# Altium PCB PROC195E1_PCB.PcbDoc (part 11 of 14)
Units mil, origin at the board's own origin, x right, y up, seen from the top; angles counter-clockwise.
Board outline 3110.24 x 2500 mil, 10 copper layers (Top Layer, L02_GND1, L03_SIG1, L04_GND2, L05_PWR1, L06_PWR2, L07_GND3, L08_SIG2, L09_GND4, Bottom Layer), stack 66.407 mil thick; 571 components, 538 nets, 6726 pads, 1286 vias.
Unrouted connection lines stored in the file: 4.
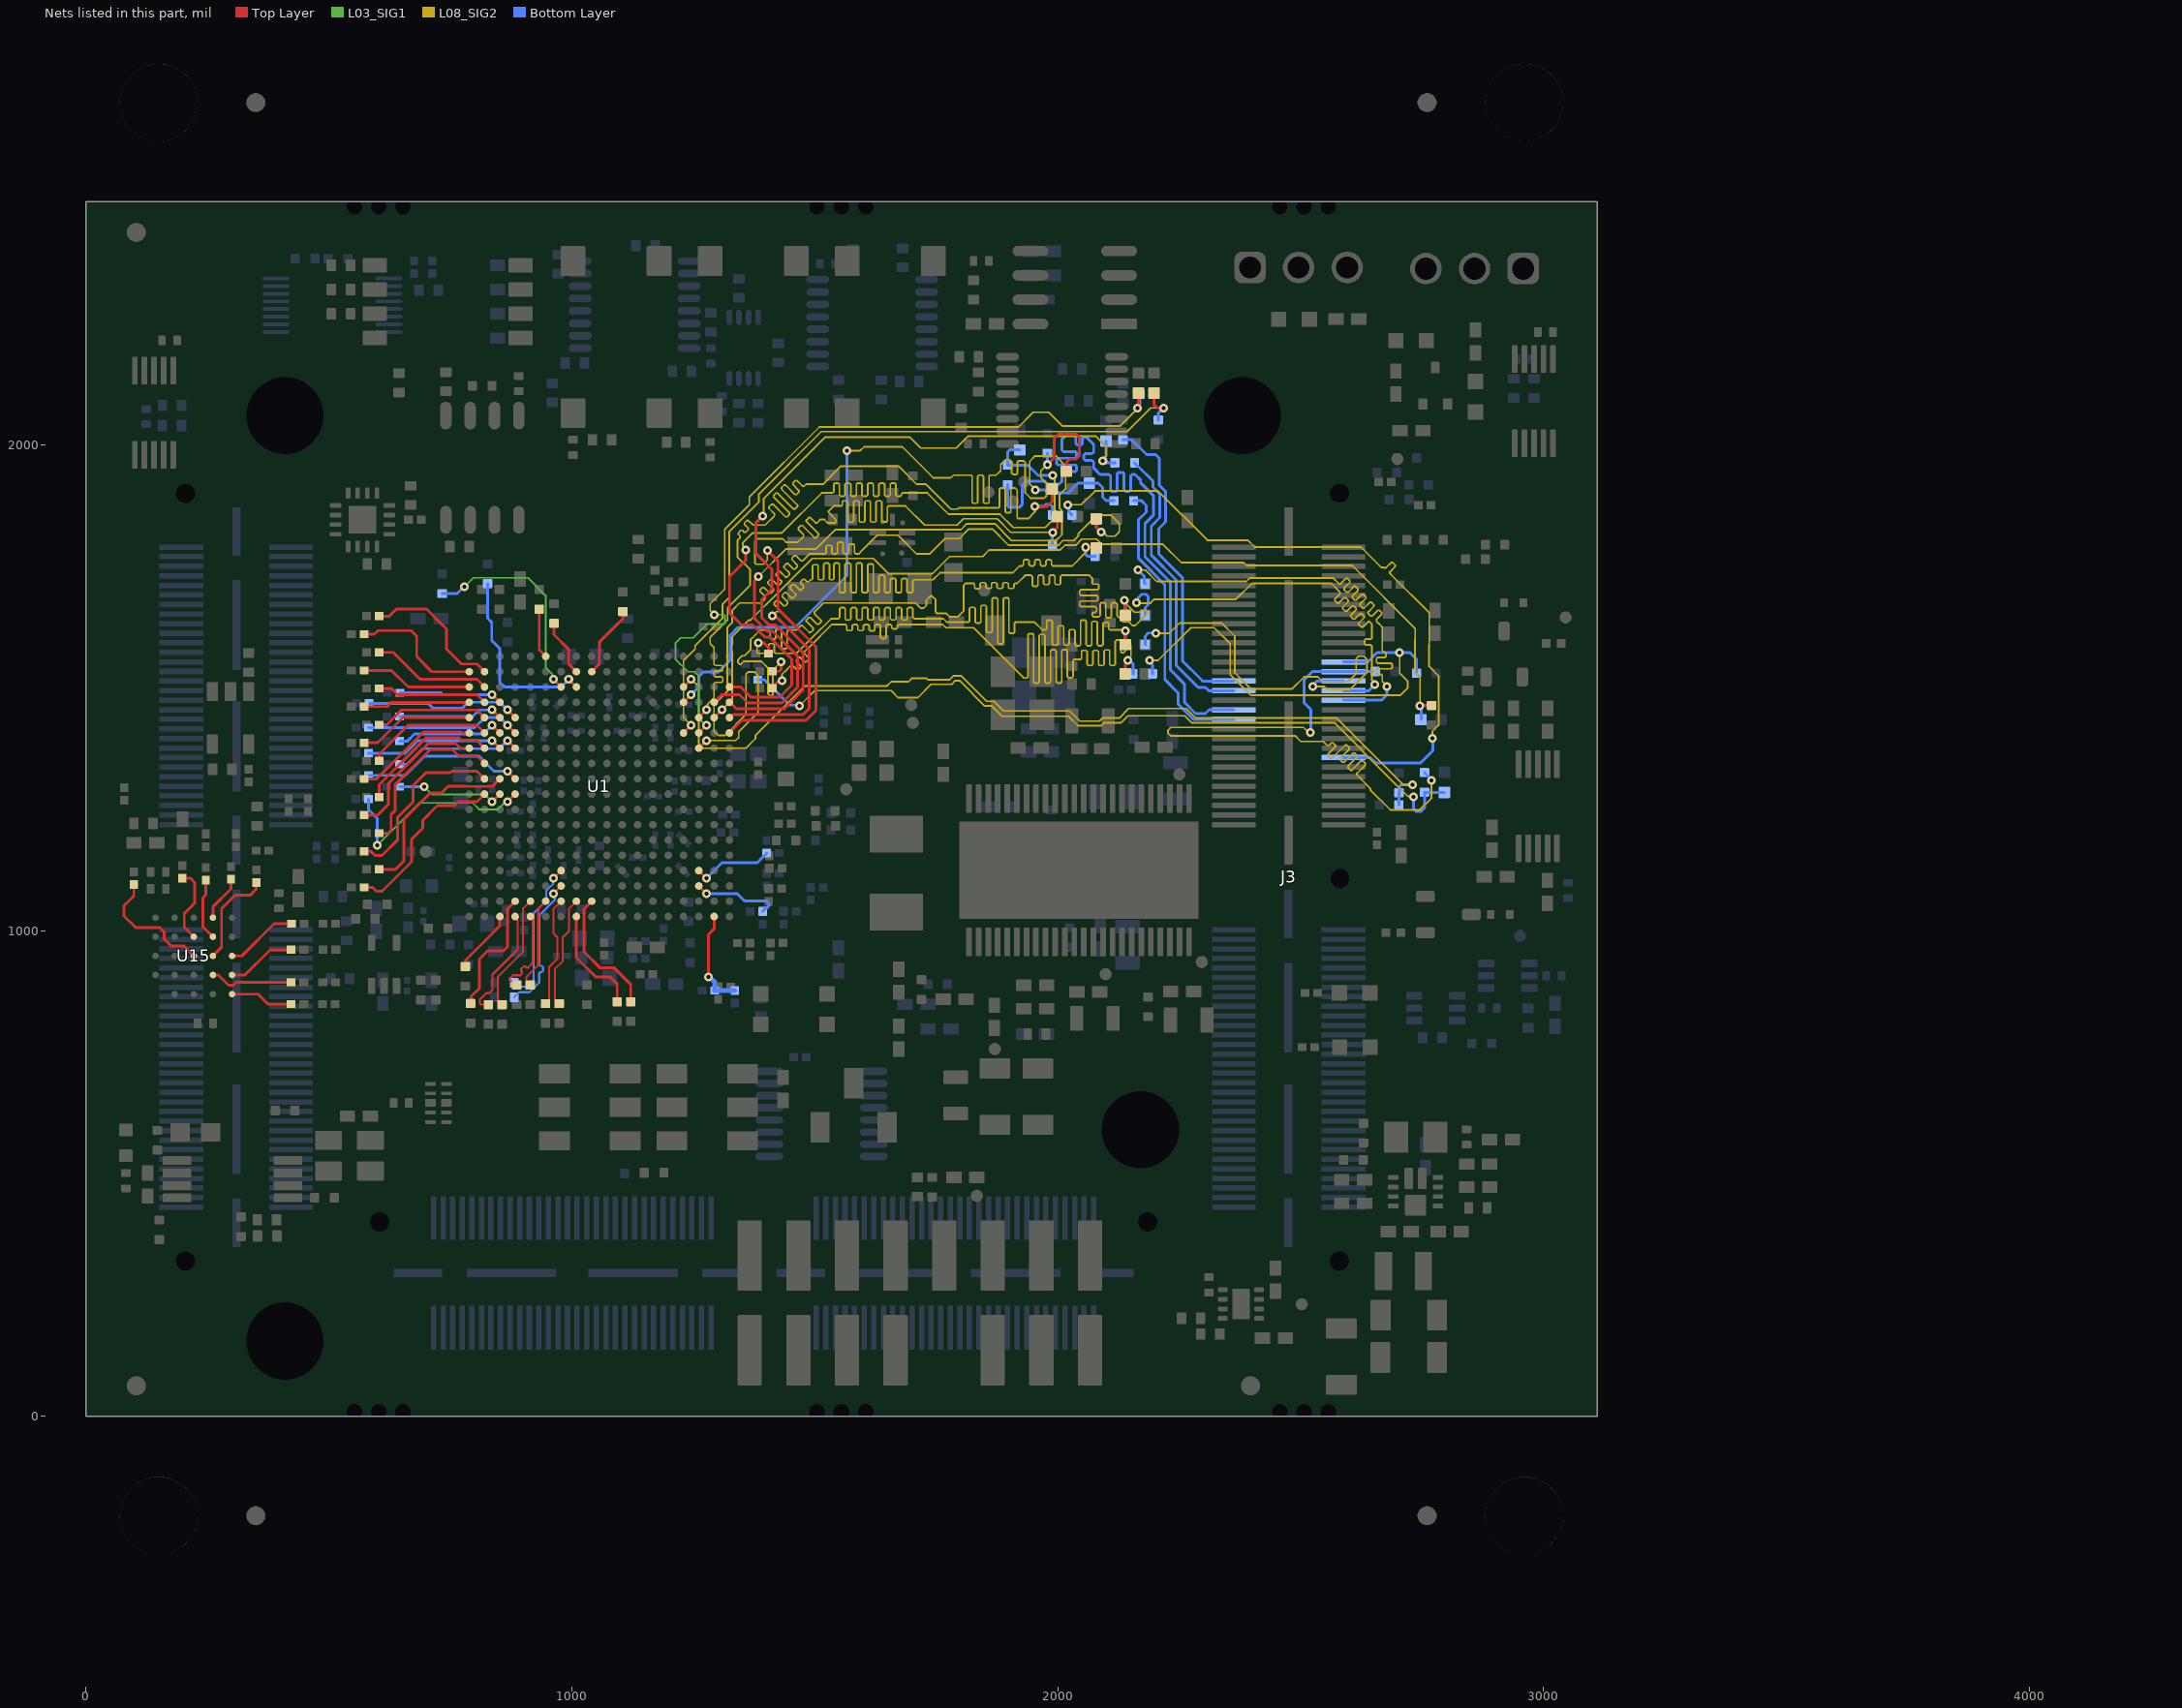
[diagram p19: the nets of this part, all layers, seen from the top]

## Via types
v1: diameter 18, hole 8, Top Layer to Bottom Layer, tented both sides, 1226 vias
v2: diameter 19.68, hole 7.87, Top Layer to Bottom Layer, tented top, 54 vias
v3: diameter 19.68, hole 7.87, Top Layer to Bottom Layer, 4 vias
v4: diameter 19.68, hole 7.87, Top Layer to Bottom Layer, tented both sides, 2 vias

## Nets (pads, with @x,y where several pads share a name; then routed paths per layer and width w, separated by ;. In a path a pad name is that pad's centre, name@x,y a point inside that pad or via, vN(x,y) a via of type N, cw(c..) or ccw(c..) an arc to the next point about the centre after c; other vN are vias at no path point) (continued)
PR0_PRU1_GPIO6: J3.76 R155.1 | length 1415.1
  L08_SIG2 w3.6: v1(2020.51,1876.46) 2048.46,1876.46 2076.8,1904.8 2206.68,1904.8 2307.9,1803.58 2391.23,1803.58 2405.46,1789.35 2624.02,1789.35 2665.54,1747.83 2670.82,1747.83 2672.1,1746.56 2675.38,1746.56 2686.24,1757.42 2689.52,1757.42 2694.44,1752.5 2694.44,1749.22 2683.58,1738.36 2683.58,1735.08 2685.81,1732.85 2687.08,1731.58 2764.58,1654.08 2764.58,1588.02 2763.9,1587.34 2763.9,1544.51 2784,1524.41 2784,1422.93 2771.15,1410.07 v1(2771.15,1396.22)
  Bottom Layer w5.8: v1(2020.51,1876.46) 2022.84,1874.13 2022.84,1862 R155.1@2029.24,1855.61 ; J3.76@2588.19,1356.08 2643.71,1356.08 2654.43,1345.36 2747.04,1345.36 2771.72,1370.04 2771.72,1395.65 v1(2771.15,1396.22)
PR0_PRU1_GPIO8: J3.89 R156.1 | length 607.7
  Bottom Layer w5.8: R156.1@2158.55,1962.95 2158.55,1962.14 2164.67,1956.01 2165.49,1956.01 2196.25,1925.25 2196.25,1912.75 2210.41,1898.59 2210.41,1850.03 2192.74,1832.37 2192.74,1773.16 2244.19,1721.71 2244.19,1545.79 2289.42,1500.56 2304.16,1500.56 2310.84,1493.88 J3.89@2362.59,1493.88
PR0_PRU1_GPIO9: J3.85 R159.1 | length 1470.9
  Bottom Layer w5.8: R159.1@1897.01,1917.7 1897.01,1874.35 1899.88,1871.47 1921.5,1871.47 1926.78,1876.76 1926.78,1915.81 1936.01,1925.04 1973.96,1925.04 1980.06,1918.94 2003.05,1918.94 2008.61,1924.49 2008.61,1941.2 2012.01,1944.59 2036.19,1944.59 2038.95,1947.35 2038.95,1955.63 2036.19,1958.39 2000.66,1958.39 1997.9,1961.15 1997.9,1969.43 2000.66,1972.19 2036.19,1972.19 2038.95,1974.95 2038.95,1983.23 2036.19,1985.99 2012.01,1985.99 2008.61,1989.39 2008.61,2005.57 2008.61,2011.34 2017.14,2019.87 2033.84,2019.87 2037.24,2016.47 2037.24,2002.63 2040,1999.87 2048.28,1999.87 2051.04,2002.63 2051.04,2012.36 2054.44,2015.76 2059.24,2015.76 2063.73,2011.28 2073.3,2001.7 2074.04,2000.96 2074.04,1985 2070.65,1981.6 2056.8,1981.6 2054.04,1978.84 2054.04,1970.56 2056.8,1967.8 2070.65,1967.8 2074.04,1964.4 2074.04,1961.32 2074.04,1952.3 2087.21,1939.14 2088.85,1939.14 2105.55,1939.14 2108.95,1935.75 2108.95,1907.19 2111.71,1904.43 2119.99,1904.43 2122.75,1907.19 2122.75,1940.45 2125.51,1943.21 2133.79,1943.21 2136.55,1940.45 2136.55,1907.19 2139.31,1904.43 2147.59,1904.43 2150.35,1907.19 2150.35,1935.75 2153.74,1939.14 2159,1939.14 2170.7,1927.44 2170.7,1921.61 2196.84,1895.47 2196.84,1854.85 2179.74,1837.75 2179.74,1769.47 2232.39,1716.82 2232.39,1536.07 2260.6,1507.86 2260.6,1470.37 2284.14,1446.83 2304.04,1446.83 2311.72,1454.51 J3.85@2362.59,1454.51
PR0_PRU1_GPIO10: J3.83 R161.1 | length 606.3
  Bottom Layer w5.8: R161.1@2156.3,1884.68 2172.55,1884.68 2182.04,1875.2 2182.04,1861.42 2166.63,1846.01 2166.63,1765.9 2220.59,1711.93 2220.59,1516.72 2247.6,1489.71 2247.6,1466.68 2279.46,1434.82 J3.83@2362.59,1434.82
PR0_PRU1_GPIO11: J3.90 R163.1 | length 974.2
  L08_SIG2 w3.6: v1(2162.42,1674.75) 2163.1,1674.08 2190.92,1674.08 2198.91,1682.07 2367.15,1682.07 2399.78,1714.7 2563.02,1714.7 2571.84,1705.89 2573.11,1704.61 2581.31,1696.41 2581.31,1693.13 2570.45,1682.27 2570.45,1678.99 2575.37,1674.07 2578.65,1674.07 2589.51,1684.93 2592.79,1684.93 2597.72,1680.01 2597.72,1676.72 2586.86,1665.86 2586.86,1662.58 2591.78,1657.66 2595.06,1657.66 2605.92,1668.52 2609.2,1668.52 2614.12,1663.6 2614.12,1660.32 2603.26,1649.46 2603.26,1646.18 2608.18,1641.26 2611.46,1641.26 2622.32,1652.12 2625.6,1652.12 2630.53,1647.2 2630.53,1643.91 2619.66,1633.05 2619.66,1629.77 2624.59,1624.85 2627.87,1624.85 2638.73,1635.71 2642.01,1635.71 2644.09,1633.63 2645.36,1632.36 2646.4,1631.32 2646.4,1629.4 ; 2646.31,1629.31 2646.31,1615.52 2646.31,1602.12 2643.99,1599.8 2633.65,1599.8 2631.33,1597.48 2631.33,1590.52 2633.65,1588.2 2643.99,1588.2 2646.31,1585.88 2646.31,1580 2646.31,1516.17 2652.54,1509.94 v1(2652.54,1506.86)
  Bottom Layer w5.8: v1(2162.42,1674.75) 2164.76,1677.09 2164.76,1683.91 2173.11,1692.26 2181.74,1692.26 2186,1688 2186,1671 2179.97,1664.97 R163.1@2179.97,1648.62 ; J3.90@2588.19,1493.88 2640.61,1493.88 2652.54,1505.81 v1(2652.54,1506.86)
PR0_PRU1_GPIO12: J3.92 R164.1 | length 869.1
  L08_SIG2 w3.6: v1(2202.52,1611.62) 2202.95,1612.04 2229.72,1612.04 2250.92,1633.24 2337.42,1633.24 2364.63,1606.03 2364.63,1530.49 2397.95,1497.17 2482.06,1497.17 2507.26,1522.38 2535.55,1522.38 2544.92,1513 2598.55,1513 2614,1528.45 2614,1559.47 2619.41,1564.87 2629.8,1564.87 2636.71,1557.96 2636.71,1531.71 2601,1496 2555,1496 2548.67,1502.33 2524.83,1502.33 v1(2524.57,1502.58)
  Bottom Layer w5.8: R164.1@2179.97,1588.62 2179.97,1606.28 2186.2,1612.51 2201.63,1612.51 v1(2202.52,1611.62) ; v1(2524.57,1502.58) 2524.57,1504.81 2533.32,1513.56 J3.92@2588.19,1513.56
PR0_PRU1_GPIO13: J3.94 R8.1 R167.1 | length 1459.6
  L08_SIG2 w3.6: v1(2520.02,1407.99) 2516.28,1407.99 2506.07,1418.19 2232.68,1418.19 2227,1412.51 2227,1406.4 2232.46,1400.94 2488.62,1400.94 2500.15,1389.41 2546.79,1389.41 2552.65,1383.55 2553.93,1382.27 2554.96,1381.24 2558.24,1381.24 2563.49,1386.5 2566.77,1386.5 2571.69,1381.58 2571.69,1378.3 2556.49,1363.09 2556.49,1359.81 2561.41,1354.89 2564.69,1354.89 2591.71,1381.91 2594.99,1381.91 2599.91,1376.98 2599.91,1373.7 2581.16,1354.95 2581.16,1351.67 2586.08,1346.75 2589.36,1346.75 2608.11,1365.5 2611.39,1365.5 2616.32,1360.58 2616.32,1357.3 2597.56,1338.55 2597.56,1335.26 2602.48,1330.34 2605.77,1330.34 2624.52,1349.1 2627.8,1349.1 2632.72,1344.17 2632.72,1340.89 2615.65,1323.83 2615.65,1320.55 2623.86,1312.34 2625.13,1311.07 2643.49,1292.71 2643.49,1289.34 2684.37,1248.46 2744.96,1248.46 2769.34,1272.83 v1(2769.33,1309.07)
  Bottom Layer w5.8: v1(2520.02,1407.99) 2521.16,1409.12 2521.16,1454.98 2506.67,1469.46 2506.67,1515.29 2524.64,1533.25 J3.94@2588.19,1533.25 R8.1@2648.07,1533.23 ; R167.1@2754.95,1325.28 2755.44,1325.28 2769.33,1311.39 v1(2769.33,1309.07)
PR0_PRU1_GPIO14: J3.96 R5.1 R169.1 | length 962.7
  L08_SIG2 w3.6: v1(2189.03,1556.43) 2207.13,1556.43 2274.34,1623.64 2321.75,1623.64 2355.03,1590.36 2355.03,1526.51 2396.83,1484.71 2706.02,1484.71 2720.23,1498.92 2720.23,1513.65 2703.82,1530.06 v1(2703.82,1572.01)
  Bottom Layer w5.8: v1(2189.03,1556.43) 2189.03,1553.62 2195.42,1547.23 R169.1@2195.42,1528.68 ; J3.96@2588.19,1552.93 2588.64,1553.38 2638.49,1553.38 2657.12,1572.01 v1(2703.82,1572.01) 2724.99,1572.01 2738.54,1558.46 R5.1@2738.54,1529.81
PR0_PRU1_GPIO15: J3.91 R170.1 | length 662
  Bottom Layer w5.8: R170.1@2134.23,2010.35 2152.6,2010.35 2183.43,1979.52 2189.7,1979.52 2201.69,1979.5 2209.1,1972.09 2209.1,1916.59 2222.21,1903.48 2222.21,1841.11 2208.23,1827.14 2208.23,1775.11 2256.6,1726.75 2256.6,1555.38 2294.73,1517.25 2298.35,1513.62 2306.41,1513.62 2306.47,1513.56 J3.91@2362.59,1513.56
PR0_PRU1_GPIO16: J3.88 R171.1 | length 1100.6
  L08_SIG2 w3.6: v1(2164.93,1742.28) 2180.51,1742.28 2204.03,1718.75 2388.56,1718.75 2395.28,1725.47 2567.52,1725.47 2577.76,1715.24 2579.03,1713.96 2582.31,1713.96 2593.17,1724.83 2596.45,1724.83 2601.38,1719.9 2601.38,1716.62 2589.67,1704.91 2589.67,1701.63 2594.59,1696.71 2597.87,1696.71 2609.58,1708.42 2612.86,1708.42 2617.78,1703.5 2617.78,1700.22 2606.07,1688.51 2606.07,1685.23 2610.99,1680.31 2614.27,1680.31 2625.98,1692.02 2629.26,1692.02 2634.19,1687.09 2634.19,1683.81 2622.48,1672.1 2622.48,1668.82 2627.4,1663.9 2630.68,1663.9 2642.39,1675.61 2645.67,1675.61 2650.59,1670.69 2650.59,1667.41 2638.88,1655.7 2638.88,1652.42 2643.8,1647.5 2647.08,1647.5 2658.79,1659.21 2662.07,1659.21 2667,1654.28 2667,1651 2656.13,1640.14 2656.13,1636.86 2661.22,1631.77 2662.5,1630.5 2668.15,1624.84 2668.15,1609.38 2668.15,1575.88 2670.47,1573.56 2672.9,1573.56 2675.22,1571.24 2675.22,1564.28 2672.9,1561.96 2658.32,1561.96 2656,1559.64 2656,1552.68 2658.32,1550.36 2685.83,1550.36 2688.15,1548.04 2688.15,1541.08 2685.83,1538.76 2658.32,1538.76 2656,1536.44 2656,1529.48 2658.32,1527.16 2665.83,1527.16 2668.15,1524.84 2668.15,1523.04 2668.15,1513.18 2677.17,1504.17 v1(2677.17,1502.58)
  Bottom Layer w5.8: v1(2164.93,1742.28) 2178.13,1729.07 2178.13,1715.76 R171.1@2179.97,1713.93 ; J3.88@2588.19,1474.19 2666.37,1474.19 2677.17,1484.99 v1(2677.17,1502.58)
R_ADC3_AIN0_P: R240.2 U1.U7 | length 230.9
  Top Layer w4.25: R240.2@946.13,849.68 946.62,849.68 953.85,856.9 953.85,859.37 ; 953.87,859.39 953.87,925.61 970.22,941.96 970.22,986.47 969.35,987.34 962.26,994.43 962.26,1044.59 U1.U7@978.14,1060.47
R_ADC3_AIN1_N: R241.2 U1.U8 | length 233.1
  Top Layer w4.25: R241.2@974.13,849.68 973.64,849.68 965.27,858.05 965.27,920.89 981.62,937.23 981.62,986.32 982.64,987.34 994.64,999.34 994.64,1045.47 U1.U8@1009.64,1060.47
R_ADC3_AIN2_P: R242.2 U1.T7 | length 294.4
  Top Layer w4.25: v1(962.39,1076.22) U1.T7@978.14,1091.97
  Bottom Layer w4.25: R242.2@881.78,862.81 881.78,863.3 891.57,873.09 913.04,873.09 933.14,893.18 933.14,898 933.14,912.38 935.63,914.87 938.69,914.87 941.14,917.32 941.14,924.67 938.69,927.12 935.63,927.12 933.14,929.61 933.14,940.26 933.14,987.34 933.14,1031.17 965.47,1063.51 965.47,1066.93 965.02,1067.38 965.02,1073.59 v1(962.39,1076.22)
R_ADC3_AIN3_N: R243.2 U1.R7 | length 298.4
  Top Layer w4.25: v1(962.39,1107.71) U1.R7@978.14,1123.46
  Bottom Layer w4.25: R243.2@881.78,892.26 881.78,891.77 889.01,884.55 891.44,884.55 891.5,884.49 908.32,884.49 921.74,897.91 921.74,987.34 921.74,1035.89 948.42,1062.58 948.42,1069.65 947.87,1070.2 947.87,1082.23 961.3,1095.67 961.3,1106.62 v1(962.39,1107.71)
R_ADC3_AIN4: R244.2 U1.V8 | length 227.6
  Top Layer w5.8: U1.V8@1009.64,1028.97 1009.64,987.34 1009.64,944.64 1050.08,904.2 1079.54,904.2 1093.49,890.25 R244.2@1093.49,853.38
R_ADC3_AIN5: R272.2 U1.U9 | length 270.5
  Top Layer w5.66: 1025.34,996 1025.34,1035.48
  Top Layer w5.8: 1025.34,996 1025.3,995.96 1025.3,987.34 1025.3,956.48 1058.62,923.15 1087.6,923.15 1121.49,889.26 R272.2@1121.49,853.38 ; 1025.34,1035.48 1025.3,1035.52 1025.3,1044.63 U1.U9@1041.13,1060.47
R_ADC4_AIN0_P: R273.2 U1.U6 | length 192.8
  Top Layer w4.25: R273.2@914.72,888.05 914.23,888.05 907.01,895.28 907.01,897.18 906.42,897.76 906.42,904.25 931.24,929.07 931.24,987.34 931.24,1045.07 U1.U6@946.64,1060.47
R_ADC4_AIN1_N: R274.2 U1.V5 | length 190.5
  Top Layer w4.25: R274.2@886.72,888.05 879.5,895.28 874.71,895.28 872.22,897.76 872.22,901.29 879.09,908.15 894.2,908.15 896.4,910.36 897.91,911.86 897.91,915.38 895.74,917.54 895.74,921.01 900.94,926.21 904.41,926.21 906.57,924.04 910.09,924.04 919.37,933.33 919.84,933.79 919.84,987.34 919.84,1021.17 915.15,1025.86 U1.V5@915.15,1028.97
R_ADC4_AIN2_P: R275.2 U1.V4 | length 235.4
  Top Layer w4.25: R275.2@828.55,847.55 813.44,847.55 810.95,850.04 810.95,857.95 824.12,871.12 830.12,871.12 836.85,877.85 836.85,909.64 888.71,961.5 888.71,1020.8 883.65,1025.86 U1.V4@883.65,1028.97
R_ADC4_AIN3_N: R276.2 U1.U5 | length 244.4
  Top Layer w4.25: R276.2@856.55,847.55 856.06,847.55 848.84,854.78 848.84,856.69 848.25,857.27 848.25,904.92 900.11,956.78 900.11,987.34 900.11,1045.43 U1.U5@915.15,1060.47
R_ADC4_AIN4: R277.2 U1.V3 | length 132.5
  Top Layer w5.6: R277.2@781.1,925.96 781,926.06 781,938.44 829.9,987.34 852.16,1009.6 U1.V3@852.16,1028.97
R_ADC4_AIN5: R278.2 U1.U4 | length 267.9
  Top Layer w5.66: 867.95,987.34 867.95,1044.7
  Top Layer w5.8: R278.2@791.99,849.9 793.25,851.16 793.25,864.55 810.02,881.32 810.02,941.52 826.79,958.28 860.01,958.28 867.95,966.22 867.95,987.34 ; 867.95,1044.7 U1.U4@883.65,1060.41
R_AM26x_EPWM0_A: R106.2 U1.B2 | length 300.8
  Top Layer w5.66: 772.99,1548.7 804.87,1548.7
  Top Layer w5.8: R106.2@603.64,1647.18 624.36,1647.18 639.07,1661.88 701.25,1661.88 733.48,1629.65 742.14,1620.99 742.14,1579.55 751.06,1570.64 772.99,1548.7 ; 804.87,1548.7 U1.B2@820.66,1532.91
R_AM26x_EPWM0_B: R107.2 U1.B1 | length 279.5
  Top Layer w5.8: R107.2@572.51,1609.96 593.98,1609.96 601.6,1617.58 669.41,1617.58 681,1605.99 681,1564 712.09,1532.91 U1.B1@789.16,1532.91
R_AM26x_EPWM1_A: R109.2 U1.D3 | length 213.9
  Top Layer w5.8: v1(836.41,1485.67) U1.D3@852.16,1469.92 U1.D3@852.16,1470.11
  Bottom Layer w5.8: R109.2@646.52,1489.43 720.46,1489.43 731.54,1489.43 735.31,1485.67 v1(836.41,1485.67)
R_AM26x_EPWM1_B: R111.2 U1.D2 | length 228.8
  Top Layer w5.66: 751.06,1485.67 804.91,1485.67
  Top Layer w5.8: R111.2@603.64,1498.29 629.06,1498.29 641.68,1485.67 720.46,1485.67 751.06,1485.67 ; 804.91,1485.67 U1.D2@820.66,1469.92
R_AM26x_EPWM2_A: R112.2 U1.C2 | length 246.6
  Top Layer w5.66: 720.46,1517.16 804.91,1517.16
  Top Layer w5.8: R112.2@603.64,1572.73 632.62,1572.73 688.2,1517.16 720.46,1517.16 ; 804.91,1517.16 U1.C2@820.66,1501.41
R_AM26x_EPWM2_B: R113.2 U1.C1 | length 230.8
  Top Layer w5.8: R113.2@572.51,1535.51 629.28,1535.51 663.38,1501.41 720.46,1501.41 U1.C1@789.16,1501.41
R_AM26x_EPWM3_A: R114.2 U1.E2 | length 236.1
  Top Layer w5.66: 751.06,1454.17 804.91,1454.17
  Top Layer w5.8: R114.2@603.64,1423.85 619.6,1423.85 649.92,1454.17 751.06,1454.17 ; 804.91,1454.17 U1.E2@820.66,1438.42
R_AM26x_EPWM3_B: R115.2 U1.E3 | length 219
  Top Layer w5.8: v1(836.41,1454.17) U1.E3@852.16,1438.42 U1.E3@851.84,1438.42
  Bottom Layer w5.8: R115.2@645.58,1440.58 720.46,1440.58 796.2,1440.58 809.79,1454.17 v1(836.41,1454.17)
R_AM26x_EPWM4_A: R116.2 U1.D1 | length 220.3
  Top Layer w5.8: R116.2@572.51,1461.07 620.11,1461.07 628.96,1469.92 720.46,1469.92 U1.D1@789.16,1469.92
R_AM26x_EPWM4_B: R117.2 U1.E4 | length 323.4
  Top Layer w5.8: v1(867.91,1454.17) U1.E4@883.65,1438.42
  Bottom Layer w5.8: R117.2@582.56,1467.83 705.01,1467.83 715,1457.83 720.46,1457.83 774.83,1457.83 787.03,1470.03 852.05,1470.03 v1(867.91,1454.17)
R_AM26x_EPWM5_A: R118.2 U1.F2 | length 261.9
  Top Layer w5.66: 720.46,1422.63 795.67,1422.63
  Top Layer w5.8: R118.2@603.64,1349.4 603.64,1363.19 663.08,1422.63 720.46,1422.63 ; 795.67,1422.63 804.96,1422.63 U1.F2@820.66,1406.93
R_AM26x_EPWM5_B: R120.2 U1.G2 | length 290.9
  Top Layer w5.66: 773.02,1391.18 804.91,1391.18
  Top Layer w5.8: R120.2@603.64,1274.96 603.64,1300.26 699.89,1396.5 720.46,1396.5 767.69,1396.5 773.02,1391.18 ; 804.91,1391.18 U1.G2@820.66,1375.43
R_AM26x_EPWM6_A: R123.2 U1.E1 | length 238.1
  Top Layer w5.8: R123.2@572.51,1386.62 600.76,1386.62 652.56,1438.42 751.06,1438.42 U1.E1@789.16,1438.42
R_AM26x_EPWM6_B: R125.2 U1.F3 | length 227.2
  Top Layer w5.8: v1(836.41,1422.67) U1.F3@852.16,1406.93 U1.F3@851.85,1406.93
  Bottom Layer w5.8: R125.2@645.27,1390.16 662.08,1390.16 676.47,1404.55 720.46,1404.55 818.28,1404.55 v1(836.41,1422.67)
R_AM26x_EPWM7_A: R127.2 U1.F4 | length 323.5
  Top Layer w5.8: v1(867.91,1422.67) U1.F4@883.65,1406.93
  Bottom Layer w5.8: R127.2@581.79,1417.55 720.46,1417.55 800.39,1417.55 821.18,1438.34 852.24,1438.34 v1(867.91,1422.67)
R_AM26x_EPWM7_B: R128.2 U1.F1 | length 257.4
  Top Layer w5.8: R128.2@572.51,1312.18 598.28,1312.18 695.07,1408.96 720.46,1408.96 773.42,1408.96 775.76,1406.62 U1.F1@788.86,1406.62
R_AM26x_EPWM8_A: R130.2 U1.G3 | length 289.5
  Top Layer w5.8: v1(836.41,1391.18) U1.G3@852.16,1375.43 U1.G3@852.16,1376.05
  Bottom Layer w5.8: R130.2@582.17,1365.25 657.48,1365.25 683.41,1391.18 837.03,1391.18 v1@837.71,1390.5
R_AM26x_EPWM8_B: R131.2 U1.H2 | length 350.6
  Top Layer w5.66: 767.42,1359.73 804.87,1359.73
  Top Layer w5.8: R131.2@603.64,1200.51 622.92,1200.51 628.29,1205.88 628.29,1238.72 636.37,1246.79 636.37,1299.61 709.66,1372.9 720.46,1372.9 754.25,1372.9 767.42,1359.73 ; 804.87,1359.73 U1.H2@820.66,1343.93
R_AM26x_EPWM9_A: R133.2 U1.G1 | length 306.5
  Top Layer w5.8: R133.2@572.51,1237.73 600.69,1237.73 622.6,1259.64 622.6,1302.53 704.78,1384.7 720.46,1384.7 761.31,1384.7 770.58,1375.43 U1.G1@789.16,1375.43
R_AM26x_EPWM9_B: R134.2 U1.J2 | length 377.2
  Top Layer w5.66: 753.35,1328.19 804.91,1328.19
  Top Layer w5.8: R134.2@572.51,1163.29 586.29,1163.29 595.15,1154.43 609.57,1154.43 641.29,1186.15 641.29,1232.19 673.71,1264.61 673.71,1298.54 700.61,1325.44 720.46,1325.44 749.07,1325.44 750.6,1325.44 751.06,1325.9 753.35,1328.19 ; 804.91,1328.19 U1.J2@820.66,1312.44
R_AM26x_EPWM10_A: R135.2 U1.G4 | length 264.8
  Top Layer w5.8: v1(867.91,1391.18) U1.G4@883.65,1375.43
  Bottom Layer w5.8: R135.2@645.56,1342.48 661.4,1342.48 693.22,1374.3 720.46,1374.3 851.03,1374.3 v1(867.91,1391.18)
R_AM26x_EPWM10_B: R136.2 U1.J3 | length 375.9
  Top Layer w5.66: 782.66,1296.73 827.16,1296.73
  Top Layer w5.8: R136.2@603.64,1126.07 637.48,1126.07 654.29,1142.88 654.29,1228.51 708.92,1283.14 720.46,1283.14 731.83,1283.14 745.49,1296.79 756.58,1296.79 782.6,1296.79 782.66,1296.73 ; 827.16,1296.73 827.23,1296.79 836.51,1296.79 U1.J3@852.16,1312.44
R_AM26x_EPWM12_A: R143.2 U1.K2 | length 370.9
  Top Layer w5.66: 766.44,1265.19 804.91,1265.19
  Top Layer w5.8: R143.2@572.51,1088.84 590.38,1088.84 598.22,1081.01 609.88,1081.01 670.53,1141.65 670.53,1188.25 693.26,1210.99 693.26,1226.99 723.59,1257.32 758.56,1257.32 766.44,1265.19 ; 804.91,1265.19 U1.K2@820.66,1280.94
R_AM26x_EPWM12_B: R144.2 U1.J4 | length 337.4
  Top Layer w5.8: v1(867.9,1328.19) U1.J4@883.65,1312.44
  Bottom Layer w5.8: R144.2@581.79,1319.64 657.72,1319.64 697.02,1358.93 720.46,1358.93 809.41,1358.93 840.16,1328.19 v1(867.9,1328.19)
R_AM26x_EPWM13_A: R146.2 U1.K4 | length 440.3
  Top Layer w5.8: v1(867.91,1265.2) U1.K4@883.65,1280.94
  L03_SIG1 w3.6: v1(599.97,1176) 686.71,1262.75 720.46,1262.75 796.1,1262.75 809.36,1249.49 848.06,1249.49 859.25,1260.68 859.5,1260.68 864.01,1265.2 v1(867.91,1265.2)
  Bottom Layer w5.8: R146.2@581.79,1270.64 581.79,1249.21 599.97,1231.04 v1(599.97,1176)
R_AM26x_EPWM13_B: R147.2 U1.K3 | length 226.6
  Top Layer w5.8: v1(836.41,1265.2) U1.K3@852.16,1280.94
  L03_SIG1 w3.6: v1(696.64,1296.16) 696.64,1296.05 712.55,1280.14 720.46,1280.14 821.47,1280.14 v1(836.41,1265.2)
  Bottom Layer w5.8: R147.2@645.27,1296.22 645.58,1296.53 696.27,1296.53 v1(696.64,1296.16)
R_AM26x_LIN1_TXD: R211.2 U1.B9 | length 150.4
  Top Layer w5.66: 1056.85,1548.63 1056.85,1571.79
  Top Layer w5.8: U1.B9@1041.13,1532.91 1056.85,1548.63 ; 1056.85,1571.79 1056.85,1593.74 1092.75,1629.65 1105.33,1642.22 R211.2@1105.33,1656.69
R_AM26x_UART0_TXD: R208.2 U1.A6 | length 102.9
  Top Layer w5.8: R208.2@933.1,1661.69 933.1,1577.95 U1.A6@946.64,1564.41
R_AM26x_UART2_RXD: R212.2 U1.B8 | length 118.6
  Top Layer w5.66: 993.89,1548.66 993.89,1578.73
  Top Layer w5.8: R212.2@963.78,1632.48 963.78,1608.84 993.89,1578.73 ; 993.89,1548.66 U1.B8@1009.64,1532.91
R_AM26x_VREFHI_G3: R79.2 R239.2 U1.V17 | length 205.4
  Top Layer w6: v1(1281.24,904.62) 1281.24,987.34 1281.24,991.91 1293.1,1003.77 U1.V17@1293.1,1028.97
  Bottom Layer w10: v1(1281.24,904.62) 1282.77,903.08 1285.17,903.08 1294.33,893.92 1294.33,876.61 R79.2@1294.42,876.51 R239.2@1335.6,876.51
R_MCU_GPIO74: R262.2 R263.2 U1.R16 | length 167.4
  Top Layer w5.8: U1.R16@1261.61,1123.46 v1(1277.35,1107.71)
  Bottom Layer w5.8: v1(1277.35,1107.71) 1309.52,1139.88 1381.86,1139.88 1390.29,1148.32 1395.49,1153.52 1395.7,1153.52 1401.07,1158.88 R262.2@1401.07,1159.1
R_MCU_GPIO119: R93.1 R173.2 U1.D15 | length 1855
  Top Layer w5.8: U1.D15@1230.11,1469.92 v1(1245.86,1485.67) ; v1(1979,1959.31) 1992.54,1972.85 1992.54,2013.02 2001.28,2021.76 2038.35,2021.76 2044.68,2015.43 2044.68,1977.38 2037.64,1970.34 2024.92,1970.34 2017.77,1963.18 R93.1@2017.77,1945.34
  L08_SIG2 w3.6: v1(1566.04,1987.92) 1593.96,1987.92 1601.79,1995.76 1680.24,1995.76 1744.04,1931.96 1780.29,1931.96 1785.67,1937.33 1808.38,1937.33 1821.78,1937.33 1824.1,1935.01 1824.1,1881.95 1826.42,1879.63 1833.38,1879.63 1835.7,1881.95 1835.7,1935.01 1838.02,1937.33 1844.98,1937.33 1847.3,1935.01 1847.3,1881.95 1849.62,1879.63 1856.58,1879.63 1858.9,1881.95 1858.9,1935.01 1861.22,1937.33 1871,1937.33 1873.31,1937.33 1882.69,1946.71 1882.69,1959.31 1892.5,1969.11 1901.28,1969.11 1905,1965.39 1905,1942 1908,1939 1915.18,1939 1917.4,1941.23 1917.4,1964.64 1919.77,1967 1930.05,1967 1933.08,1963.97 1933.08,1901.26 1944.3,1890.04 1972.54,1890.04 1976.85,1894.34 1976.85,1920.78 1965.29,1932.35 1965.29,1945.99 1978.6,1959.31 v1(1979,1959.31)
  Bottom Layer w5.8: v1@1246.12,1485.67 1246.12,1485.93 1261.89,1501.7 1261.89,1523.5 1270.85,1532.46 1301.75,1532.46 1326,1556.71 1326,1608.11 1341.82,1623.92 1390.29,1623.92 1459.95,1623.92 1566.4,1730.37 1566.4,1987.57 v1(1566.04,1987.92) ; v1@1978.68,1959.63 1978.74,1959.69 R173.2@1978.68,1982.85 R173.2@1978.68,1982.85
R_MCU_GPIO120: R96.1 R172.2 U1.C15 | length 1881.6
  Top Layer w5.8: U1.C15@1230.11,1501.41 v1(1245.86,1517.16)
  L08_SIG2 w3.6: v1@1246.16,1517.26 1261.65,1501.76 1261.65,1384.67 1270.85,1375.48 1358.41,1375.48 1377.81,1394.88 1377.81,1401.27 1480.1,1503.56 1648.98,1503.56 1657.9,1512.47 1693.1,1512.47 1700.15,1519.52 1729.62,1519.52 1732.54,1516.6 1777.9,1516.6 1785.52,1524.22 1801.93,1524.22 1854.26,1471.89 1868.91,1471.89 1888.58,1452.22 2024.72,1452.22 2045.66,1431.27 2085.99,1431.27 2092.27,1437.54 2126.69,1437.54 2146.21,1457.06 2264.76,1457.06 2284.31,1437.51 2574.21,1437.51 2711.7,1300.03 v1(2729.9,1300.03)
  Bottom Layer w5.8: R172.2@2702.18,1258.87 R96.1@2702.18,1283.87 2703.21,1284.9 2703.21,1296.57 2706.67,1300.03 v1(2729.9,1300.03)
R_MCU_SPI3_CLK: R204.2 U1.C8 | length 388.6
  Top Layer w5.8: v1(993.89,1517.16) U1.C8@1009.64,1501.41
  Bottom Layer w5.8: R204.2@826.74,1714.27 826.74,1643.03 835.47,1634.3 835.47,1629.65 835.47,1597.23 852,1580.7 852,1511.43 862.27,1501.16 978.28,1501.16 993.89,1516.76 v1(993.89,1517.16)
R_MCU_SPI3_D0: R207.2 U1.C7 | length 443.3
  Top Layer w5.8: v1(962.39,1517.16) U1.C7@978.14,1501.41
  L03_SIG1 w3.6: v1(779.24,1707.5) 797.85,1726.11 910.05,1726.11 946.5,1689.66 946.5,1629.65 946.5,1541.76 960.16,1528.1 960.16,1518.77 v1@962.14,1516.78
  Bottom Layer w5.8: R207.2@733.39,1693.67 764.27,1693.67 778.1,1707.5 v1(779.24,1707.5)
R_MII_RXER: R4.2 R261.2 U1.T16 | length 182.2
  Top Layer w5.8: U1.T16@1261.61,1091.97 v1(1277.35,1076.22)
  Bottom Layer w5.8: v1(1277.35,1076.22) 1340.68,1076.22 1355.8,1061.1 1390.29,1061.1 1400.42,1061.1 1406.21,1055.32 1406.21,1051.26 1400.64,1045.69 1398.51,1045.69 1393.15,1040.32 R4.2@1393.15,1039.53
R_OSPI0_D0: R186.1 U15.D3 | length 205.8
  Top Layer w5.8: U15.D3@261.7,947.98 279.36,965.64 279.36,1044.85 307.12,1072.6 338.07,1072.6 350.94,1085.47 R186.1@350.94,1098.71
R_OSPI0_D1: R187.1 U15.D2 | length 172.1
  Top Layer w5.8: U15.D2@262.01,908.3 273.23,908.3 294.13,887.4 303.32,887.4 309.68,893.76 R187.1@422.82,893.76
R_OSPI0_D2: R189.1 U15.C4 | length 157.5
  Top Layer w5.8: R189.1@199,1107.71 215.48,1107.71 224.23,1098.95 224.23,1056.6 202.67,1035.04 202.67,1007.01 U15.C4@222.33,987.35
R_OSPI0_D3: R191.1 U15.D4 | length 127.3
  Top Layer w5.8: R191.1@247.18,1103.76 247.18,1073.26 241.26,1067.33 241.26,1007.79 U15.D4@261.7,987.35
R_OSPI0_D4: R193.1 U15.D5 | length 94.4
  Top Layer w5.8: U15.D5@261.7,1026.72 261.7,1048.43 298.96,1085.69 R193.1@298.96,1105.71
R_OSPI0_D5: R195.1 U15.E3 | length 149.9
  Top Layer w5.8: U15.E3@301.07,947.98 321.36,947.98 387.34,1013.96 R195.1@423.68,1013.96
R_OSPI0_D6: R196.1 U15.E2 | length 143.3
  Top Layer w5.8: U15.E2@301.07,908.61 327.41,908.61 379.43,960.62 R196.1@422.82,960.62
R_OSPI0_D7: R197.1 U15.E1 | length 130.2
  Top Layer w5.8: U15.E1@301.07,869.24 354.84,869.24 375.22,848.86 R197.1@422.82,848.86
R_OSPI0_DQS: R198.1 U15.C3 | length 258.8
  Top Layer w5.8: R198.1@99,1094.77 99,1071.61 89.42,1062.03 78.9,1051.55 78.9,1029.97 102.87,1006 152.5,1006 161.4,997.09 161.4,982.9 175.91,968.39 201.92,968.39 U15.C3@222.33,947.98
R_PR0_PRU1_GPIO0: R86.2 R149.2 U1.F18 | length 1882.1
  Top Layer w5.8: U1.F18@1324.6,1406.93 1324.6,1406.98 1350.3,1432.68 1482,1432.68 1502.62,1453.3 1502.62,1584.11 1424.4,1662.33 1424.4,1760.82 v1(1402.53,1782.69) ; v1(1989.79,1819.7) 1999.29,1829.2 R86.2@1999.29,1851.9
  L08_SIG2 w3.6: 1376.87,1800.94 1376.87,1757.04 1379.9,1754 1394,1754 1402.53,1762.53 v1(1402.53,1782.69) ; 1376.91,1800.94 1382.6,1806.63 1433.83,1806.63 1441.08,1799.37 1465.37,1799.37 1476.04,1810.04 1477.31,1811.31 1477.31,1814.59 1466.45,1825.45 1466.45,1828.73 1471.37,1833.65 1474.65,1833.65 1499.65,1808.65 1502.93,1808.65 1507.86,1813.57 1507.86,1816.85 1482.85,1841.86 1482.85,1845.14 1487.77,1850.06 1491.05,1850.06 1501.92,1839.2 1505.2,1839.2 1512.5,1846.5 1519.5,1846.5 1527,1839 1541,1839 1544.05,1842.05 1544.05,1845.2 1528.7,1860.55 1528.7,1863.7 1539,1874 1552.73,1874 1554.53,1874 1556.85,1876.32 1556.85,1882.28 1559.17,1884.6 1566.13,1884.6 1568.45,1882.28 1568.45,1843.07 1570.77,1840.75 1577.73,1840.75 1580.05,1843.07 1580.05,1882.28 1582.37,1884.6 1589.33,1884.6 1591.65,1882.28 1591.65,1843.07 1593.97,1840.75 1600.93,1840.75 1603.25,1843.07 1603.25,1882.28 1605.57,1884.6 1612.53,1884.6 1614.85,1882.28 1614.85,1843.07 1617.17,1840.75 1624.13,1840.75 1626.45,1843.07 1626.45,1882.28 1628.77,1884.6 1635.73,1884.6 1638.05,1882.28 1638.05,1843.37 1640.37,1841.05 1647.33,1841.05 1649.65,1843.37 1649.65,1871.68 1651.97,1874 1686.04,1874 1687,1874 1726.26,1834.74 1739.42,1834.74 1784.95,1834.74 1793.12,1834.74 1805.99,1847.61 1875.47,1847.61 1903.24,1819.84 v1@1989.66,1819.84
  Bottom Layer w5.8: R149.2@1989.22,1794.21 1989.22,1819.13 v1(1989.79,1819.7)
R_PR0_PRU1_GPIO1: R87.2 R150.2 U1.G16 | length 2053.7
  Top Layer w5.8: U1.G16@1261.61,1375.43 v1(1277.35,1391.18) ; R87.2@2079.58,1847.43 2079.58,1830.25 v1(2089.92,1819.9)
  L08_SIG2 w3.6: v1(1277.35,1391.18) 1337.15,1391.18 1343.52,1397.55 1343.52,1409.34 1383.35,1449.17 1383.35,1524.62 1375.39,1532.58 1363.54,1532.58 1358.8,1527.84 1358.8,1445.13 1315.49,1401.81 1301.67,1401.81 1292.95,1410.53 1292.95,1416.21 1292.95,1460.63 1292.95,1465.43 1320.35,1492.83 1320.35,1570.79 1320.29,1570.86 1320.29,1591.74 1320.35,1591.8 1320.35,1624.19 1325.8,1629.65 1330.39,1634.23 1330.39,1659.43 1345.21,1674.25 1388.92,1674.25 1397.2,1682.54 1398.48,1683.81 1398.48,1687.09 1387.61,1697.95 1387.61,1701.23 1392.54,1706.15 1395.82,1706.15 1407,1694.97 1410.28,1694.97 1415.2,1699.89 1415.2,1703.18 1404.02,1714.36 1404.02,1717.64 1408.94,1722.56 1412.22,1722.56 1423.41,1711.37 1426.69,1711.37 1431.61,1716.29 1431.61,1719.58 1420.42,1730.76 1420.42,1734.04 1425.35,1738.96 1428.63,1738.96 1439.81,1727.78 1443.09,1727.78 1448.02,1732.7 1448.02,1735.98 1436.83,1747.17 1436.83,1750.45 1441.75,1755.37 1445.03,1755.37 1456.22,1744.18 1459.5,1744.18 1464.42,1749.1 1464.42,1752.39 1453.23,1763.57 1453.23,1766.85 1458.16,1771.77 1461.44,1771.77 1472.3,1760.91 1475.58,1760.91 1490.24,1775.58 1493.11,1775.58 1519.67,1775.58 1521.47,1775.58 1523.79,1777.9 1523.79,1790.68 1526.11,1793 1533.07,1793 1535.39,1790.68 1535.39,1777.9 1537.71,1775.58 1544.67,1775.58 1546.99,1777.9 1546.99,1797.1 1549.31,1799.42 1556.27,1799.42 1558.59,1797.1 1558.59,1777.9 1560.91,1775.58 1567.87,1775.58 1570.19,1777.9 1570.19,1793.17 1572.51,1795.49 1579.47,1795.49 1581.79,1793.17 1581.79,1777.9 1584.11,1775.58 1586,1775.58 1591.37,1775.58 1593.6,1777.8 1593.6,1778.6 1628.68,1813.68 1671.31,1813.68 1709.81,1775.17 1736.17,1775.17 1767.78,1806.78 1797.54,1806.78 1817.34,1826.57 1865.96,1826.57 1899.23,1793.3 2001.35,1793.3 2010.84,1802.79 2033.08,1802.79 2042.92,1812.63 2042.92,1817.5 2080.42,1855 2110,1855 2127,1838 2127,1821 2118,1812 2101.72,1812 2093.82,1819.9 v1(2089.92,1819.9)
  Bottom Layer w5.8: R150.2@2079.85,1847.21 2079.85,1829.47 2089.41,1819.9 v1(2089.92,1819.9)
R_PR0_PRU1_GPIO2: R88.2 R151.2 U1.E17 | length 1990
  Top Layer w5.8: U1.E17@1293.1,1438.42 v1(1308.85,1454.17) ; v1(2745.68,1463) 2745.87,1463.19 2769.21,1463.19 R151.2@2769.4,1463.38
  L08_SIG2 w3.6: v1(1308.85,1454.17) 1329.95,1475.27 1329.95,1574.77 1329.89,1574.84 1329.89,1587.76 1329.95,1587.82 1329.95,1604.94 1354.66,1629.65 1364.26,1639.25 1368.13,1639.25 1426.99,1698.11 1494.87,1765.98 1595.35,1765.98 1620.74,1766 1652.34,1734.41 1741.82,1734.41 1777.57,1770.16 1845.81,1770.16 1859.34,1783.7 2005.33,1783.7 2014.82,1793.19 2037.05,1793.19 2049.59,1805.72 2080.34,1805.72 2090.78,1795.28 2216.7,1795.28 2254.39,1757.6 2382.91,1757.6 2388.99,1751.51 2606.09,1751.51 2735.78,1621.82 2735.78,1599.95 2735.1,1599.27 2735.1,1532.58 2745.65,1522.03 v1@2745.65,1463.03
  Bottom Layer w5.8: v1(2745.68,1463) 2747.89,1460.8 R88.2@2747.89,1434.44
R_PR0_PRU1_GPIO3: R89.2 R152.2 U1.E18 | length 2100
  Top Layer w5.8: U1.E18@1324.6,1438.42 1326.2,1438.42 1332.44,1444.66 1476.15,1444.66 1488.96,1457.47 1488.96,1577.96 1429.63,1637.29 1429.45,1637.29 1421.61,1645.13 1415.25,1645.13 v1(1412.92,1647.46) ; v1(2057.7,1788.92) 2078.09,1788.92 R89.2@2079.58,1787.43
  L08_SIG2 w3.6: v1(1412.92,1647.46) 1421.82,1656.37 1425.73,1656.37 1427,1657.65 1427,1660.93 1416.84,1671.09 1416.84,1674.38 1421.76,1679.3 1425.04,1679.3 1436.12,1668.21 1439.41,1668.21 1444.33,1673.13 1444.33,1676.41 1433.25,1687.49 1433.25,1690.78 1438.17,1695.7 1441.45,1695.7 1452.53,1684.61 1455.81,1684.61 1460.73,1689.54 1460.73,1692.82 1449.65,1703.9 1449.65,1707.18 1454.57,1712.1 1457.85,1712.1 1468.93,1701.02 1472.22,1701.02 1477.14,1705.94 1477.14,1709.22 1471.39,1714.96 1471.39,1718.25 1476.32,1723.17 1479.6,1723.17 1484.42,1718.34 1487.7,1718.34 1489.59,1720.24 1491.3,1721.94 ; 1491.49,1722.13 1493.29,1722.13 1495.61,1724.45 1495.61,1750.82 1497.93,1753.14 1504.89,1753.14 1507.21,1750.82 1507.21,1724.45 1509.53,1722.13 1516.49,1722.13 1518.81,1724.45 1518.81,1754.06 1521.13,1756.38 1528.09,1756.38 1530.41,1754.06 1530.41,1724.45 1532.73,1722.13 1535,1722.13 1535.33,1722.13 1537.13,1722.13 1539.45,1724.45 1539.45,1754.06 1541.77,1756.38 1548.73,1756.38 1551.05,1754.06 1551.05,1697.92 1553.37,1695.6 1560.33,1695.6 1562.65,1697.92 1562.65,1754.06 1564.97,1756.38 1571.93,1756.38 1574.25,1754.06 1574.25,1697.92 1576.57,1695.6 1583.53,1695.6 1585.85,1697.92 1585.85,1754.06 1588.17,1756.38 1595.13,1756.38 1597.45,1754.06 1597.45,1697.92 1599.77,1695.6 1606.73,1695.6 1609.05,1697.92 1609.05,1752.46 1611.37,1754.78 1618.33,1754.78 1620.65,1752.46 1620.65,1697.92 1622.97,1695.6 1629.93,1695.6 1632.25,1697.92 1632.25,1729.26 1634.57,1731.58 1641.53,1731.58 1643.85,1729.26 1643.85,1697.92 1646.17,1695.6 1653.13,1695.6 1655.45,1697.92 1655.45,1722.49 1657.77,1724.81 1664.73,1724.81 1667.05,1722.49 1667.05,1697.92 1669.37,1695.6 1676.33,1695.6 1678.65,1697.92 1678.65,1722.49 1680.97,1724.81 1687.93,1724.81 1690.25,1722.49 1690.25,1697.92 1692.57,1695.6 1699.53,1695.6 1701.85,1697.92 1701.85,1719.81 1704.17,1722.13 1707.53,1722.13 1743.44,1722.13 1757.87,1736.56 1790.23,1736.56 1908.01,1736.56 1922.04,1750.59 1925.46,1750.59 1927.27,1750.59 1929.59,1752.91 1929.59,1761.16 1931.91,1763.48 1938.87,1763.48 1941.19,1761.16 1941.19,1752.91 1943.51,1750.59 1950.47,1750.59 1952.79,1752.91 1952.79,1761.16 1955.11,1763.48 1962.07,1763.48 1964.39,1761.16 1964.39,1752.91 1966.71,1750.59 1973.67,1750.59 1975.99,1752.91 1975.99,1761.16 1978.31,1763.48 1985.27,1763.48 1987.59,1761.16 1987.59,1752.91 1989.91,1750.59 2002.86,1750.59 2029.91,1750.59 2056.3,1776.99 2056.3,1787.53 v1(2057.7,1788.92)
  Bottom Layer w5.8: v1(2057.7,1788.92) 2058.17,1788.44 2058.17,1773.74 2061.57,1770.34 R152.2@2077.2,1770.34
R_PR0_PRU1_GPIO4: R103.1 R153.2 U1.F16 | length 1623.9
  Top Layer w5.8: U1.F16@1261.61,1406.93 v1(1277.35,1422.67) ; v1(2164.48,2075.29) 2166.21,2077.02 R103.1@2166.21,2106.39
  L03_SIG1 w3.6: v1@1276.67,1421.37 1261.59,1436.45 1261.59,1523.49 1252.32,1532.76 1251.98,1532.76 1251.78,1532.96 1239.5,1532.96 1213.48,1558.97 1213.48,1591.8 1224.3,1602.61 1249.95,1602.61 1276.98,1629.65 1278.09,1630.76 1313.26,1630.76 1315.36,1632.86 1315.36,1648.15 1313.26,1650.26 v1(1293.21,1650.26)
  L08_SIG2 w3.6: v1(1293.21,1650.26) 1293.21,1650.73 1284.75,1659.19 1284.75,1672.81 1314.69,1702.75 1314.69,1825.5 1365.73,1876.53 1365.73,1892.71 1509.62,2036.6 1919.58,2036.6 1949.9,2066.92 1981.57,2066.92 2010.17,2038.32 2127.51,2038.32 v1(2164.48,2075.29)
  Bottom Layer w5.8: v1(2164.48,2075.29) 2164.48,2078.59 2169.4,2083.51 R153.2@2169.4,2104.28
R_PR0_PRU1_GPIO5: R98.1 R154.2 U1.F15 | length 1551
  Top Layer w5.8: U1.F15@1230.11,1406.93 v1(1245.86,1422.67) ; R98.1@2198.4,2106.23 2198.4,2082.79 2205.86,2075.32 v1@2217.71,2075.32
  L08_SIG2 w3.6: v1(1245.86,1422.67) 1229.91,1438.62 1229.91,1447.52 1230.06,1447.67 1230.06,1510.66 1230.06,1523.66 1229.91,1523.82 1229.91,1555.35 1253.87,1579.31 1253.87,1586.23 1310.01,1642.37 1310.01,1671.76 1324.55,1686.3 1324.55,1821.78 1385.14,1882.36 1385.14,1898.54 1513.6,2027 2142.7,2027 2191.43,2075.73 v1(2218.11,2075.73)
  Bottom Layer w5.8: R154.2@2207.4,2050.91 2207.14,2051.16 2207.14,2065.05 2217.82,2075.73 v1(2218.11,2075.73)
R_PR0_PRU1_GPIO6: R102.1 R155.2 U1.E16 | length 1842.1
  Top Layer w5.8: U1.E16@1261.61,1438.42 v1(1277.35,1454.17) ; v1(1953.42,1873.24) 1953.58,1873.39 1979.13,1873.39 1988.73,1883 R102.1@1988.73,1909.03
  L08_SIG2 w3.6: v1@1276.77,1452.96 1279.22,1455.41 1279.22,1465.47 1292.95,1479.2 1292.95,1485.06 1292.95,1495.26 1292.95,1508.66 1295.27,1510.98 1308.37,1510.98 1310.69,1513.3 1310.69,1520.26 1308.37,1522.58 1295.11,1522.58 1292.79,1524.9 1292.79,1531.86 1295.11,1534.18 1308.37,1534.18 1310.69,1536.5 1310.69,1543.46 1308.37,1545.78 1295.27,1545.78 1292.95,1548.1 1292.95,1556.62 1292.95,1582.8 1284.92,1590.83 1284.92,1603.71 1320.79,1639.58 1320.79,1664.38 1367.28,1710.87 1367.28,1742.73 1340.99,1769.02 1340.99,1803.07 1345.39,1807.48 1346.66,1808.75 1346.66,1812.03 1343.13,1815.56 1343.13,1818.84 1348.05,1823.76 1351.34,1823.76 1354.87,1820.23 1358.15,1820.23 1363.07,1825.16 1363.07,1828.44 1355.57,1835.94 1355.57,1839.22 1360.49,1844.14 1363.77,1844.14 1373.17,1834.74 1376.26,1834.74 1398.06,1834.74 1416.29,1852.97 1417.56,1854.24 1417.56,1857.52 1405.98,1869.1 1405.98,1872.39 1410.9,1877.31 1414.18,1877.31 1439.91,1851.58 1443.19,1851.58 1448.11,1856.5 1448.11,1859.78 1415.46,1892.43 1415.46,1895.72 1420.38,1900.64 1423.66,1900.64 1456.31,1867.98 1459.59,1867.98 1464.51,1872.91 1464.51,1876.19 1431.86,1908.84 1431.86,1912.12 1436.78,1917.04 1440.06,1917.04 1459.46,1897.65 1462.74,1897.65 1467.66,1902.57 1467.66,1905.85 1455.43,1918.08 1455.43,1921.36 1460.35,1926.28 1463.63,1926.28 1474.98,1914.94 1478.26,1914.94 1482,1918.67 1516.67,1918.67 1554,1956 1672.48,1956 1709.81,1918.67 1729.49,1918.67 1780.42,1867.75 1794.34,1867.75 1796.62,1870.03 1876.22,1870.03 ; 1876.32,1869.94 1878.12,1869.94 1880.44,1872.26 1880.44,1908.87 1882.76,1911.19 1889.72,1911.19 1892.04,1908.87 1892.04,1862.21 1894.36,1859.89 1901.32,1859.89 1903.64,1862.21 1903.64,1869.59 1903.64,1876.97 1903.64,1907.64 1907,1911 1912.77,1911 1916.83,1906.94 1916.83,1850.23 1919.06,1848 1939.35,1848 1952.8,1861.45 1952.8,1872.61 v1(1953.42,1873.24)
  Bottom Layer w5.8: v1@1953.55,1873.37 1971.32,1873.37 1975.29,1877.34 1985.16,1877.34 1988.93,1873.58 R155.2@1988.93,1855.57
R_PR0_PRU1_GPIO8: R101.1 R156.2 U1.D18 | length 1526.4
  Top Layer w5.8: U1.D18@1324.6,1469.92 1325.02,1469.92 1338.02,1456.92 1437.78,1456.92 1476.25,1495.39 1476.25,1572.1 1419.7,1628.65 1406.41,1628.65 1390.98,1644.09 1390.98,1681.19 1412.15,1702.36 1412.15,1743.34 1379.44,1776.05 1379.44,1839.88 v1(1392.56,1852.99)
  L08_SIG2 w3.6: v1(1392.56,1852.99) 1394.74,1855.17 1394.74,1888.57 1522.02,2015.85 1695.35,2015.85 1717.99,1993.21 1791.02,1993.21 1815.21,2017.4 2078.71,2017.4 2100,1996.12 2100,1976.63 2093,1969.63 v1(2093,1966.81)
  Bottom Layer w5.8: R101.1@2099.5,2007.78 2099.5,1976.61 2093,1970.11 v1(2093,1966.81) 2095.73,1966.81 2099.59,1962.95 R156.2@2117.87,1962.95
R_PR0_PRU1_GPIO9: R99.1 R159.2 U1.C18 | length 1781.8
  Top Layer w5.8: U1.C18@1324.6,1501.41 1347.77,1501.41 1368.66,1480.52 1428.01,1480.52 1452.65,1505.16 1452.65,1558.93 1407.28,1604.3 1397.39,1604.3 1372.2,1629.49 1349.22,1629.49 1349.06,1629.65 1324.78,1653.93 1324.78,1728.65 1358.45,1762.32 v1(1358.45,1783.2)
  L08_SIG2 w3.6: v1(1358.45,1783.2) 1358.45,1786.02 1351.96,1792.51 1351.96,1797.74 1372.81,1818.59 1432.32,1818.59 1514.73,1901 1535.34,1901 1537.14,1901 1539.46,1903.32 1539.46,1918.68 1541.78,1921 1548.74,1921 1551.06,1918.68 1551.06,1896.52 1553.38,1894.2 1560.34,1894.2 1562.66,1896.52 1562.66,1918.68 1564.98,1921 1571.94,1921 1574.26,1918.68 1574.26,1896.52 1576.58,1894.2 1583.54,1894.2 1585.86,1896.52 1585.86,1918.68 1588.18,1921 1595.14,1921 1597.46,1918.68 1597.46,1896.52 1599.78,1894.2 1606.74,1894.2 1609.06,1896.52 1609.06,1918.68 1611.38,1921 1618.34,1921 1620.66,1918.68 1620.66,1896.52 1622.98,1894.2 1629.94,1894.2 1632.26,1896.52 1632.26,1918.68 1634.58,1921 1641.54,1921 1643.86,1918.68 1643.86,1896.52 1646.18,1894.2 1653.14,1894.2 1655.46,1896.52 1655.46,1918.68 1657.78,1921 1664.74,1921 1667.06,1918.68 1667.06,1896.52 1669.38,1894.2 1676.34,1894.2 1678.66,1896.52 1678.66,1898.68 1680.98,1901 1685,1901 1731.7,1901 1775.48,1857.21 1881.14,1857.21 1908.46,1829.89 1974.35,1829.89 1994.11,1849.65 1994.11,1928.79 1989.96,1932.94 v1(1989.96,1936.84)
  Bottom Layer w5.8: R99.1@1922,1989.33 1900.91,1989.33 1897.01,1985.43 R159.2@1897.01,1958.05 1938.55,1958.05 1959.76,1936.84 v1(1989.96,1936.84)
R_PR0_PRU1_GPIO10: R100.1 R161.2 U1.D17 | length 1660.4
  Top Layer w5.66: 1308.84,1485.65 1345.15,1485.65
  Top Layer w5.8: U1.D17@1293.1,1469.92 1308.85,1485.67 ; 1345.15,1485.65 1362.08,1468.72 1390.29,1468.72 1432.9,1468.72 1464.45,1500.27 1464.45,1565.52 1413.87,1616.1 1402.28,1616.1 1390.29,1628.09 1388.73,1629.65 1375.99,1642.39 1375.99,1720.35 1384.08,1728.44 v1(1384.08,1728.71)
  L08_SIG2 w3.6: v1(1384.08,1728.71) 1440.55,1785.18 1502.39,1785.18 1542.27,1825.06 1800.55,1825.06 1812.86,1837.37 1870.43,1837.37 1904.91,1802.9 1996.75,1802.9 2008.81,1814.96 2008.81,1864.4 2003.71,1869.5 2003.71,1896.84 2016.28,1909.41 2016.28,1956.7 1996.04,1976.95 1953.9,1976.95 1942.68,1965.73 1942.68,1919.32 1954.17,1907.83 v1(1954.17,1906.84)
  Bottom Layer w5.8: v1(1954.17,1906.84) 1954.67,1907.34 1973.27,1907.34 1979.33,1901.29 2022.4,1901.29 2041.8,1920.69 R100.1@2065.1,1920.69 2083.78,1920.69 2092.77,1911.7 2092.77,1892.25 2100.34,1884.68 R161.2@2115.95,1884.68
R_PR0_PRU1_GPIO11: R92.2 R137.1 R163.2 | length 2133.7
  Top Layer w5.8: R137.1@1412.85,1533.91 1427.41,1533.91 1430.81,1537.31 v1(1430.81,1553.13) ; v1(2137.4,1679.73) 2139.04,1678.09 R92.2@2139.04,1648.71
  L08_SIG2 w3.6: v1(1430.81,1553.13) 1413.95,1536.27 1413.95,1485.74 1411.72,1483.51 1408.58,1483.51 1403.75,1488.33 1403.75,1540.72 1390.29,1554.18 1354.18,1554.18 1348.57,1548.57 1345.43,1548.57 1342.09,1551.91 1342.09,1556.92 1350.76,1565.6 1355.6,1565.6 1368,1578 1368,1598.95 1377.99,1608.94 1377.99,1609.04 1387.39,1618.44 1392.76,1618.44 1406.16,1618.44 1408.48,1616.12 1408.48,1602.55 1410.8,1600.23 1417.76,1600.23 1420.08,1602.55 1420.08,1618.15 1422.4,1620.47 1429.36,1620.47 1431.68,1618.15 1431.68,1582.55 1434,1580.23 1440.96,1580.23 1443.28,1582.55 1443.28,1616.12 1445.6,1618.44 1459,1618.44 1462.02,1618.44 1471.49,1627.91 1474.78,1627.91 1488.7,1613.99 1491.98,1613.99 1496.9,1618.91 1496.9,1622.19 1482.98,1636.12 1482.98,1639.4 1487.9,1644.32 1491.18,1644.32 1505.1,1630.39 1508.39,1630.39 1513.31,1635.31 1513.31,1638.6 1499.38,1652.52 1499.38,1655.8 1504.69,1661.11 1518.06,1674.48 1707.1,1674.48 1717.93,1663.65 1723.81,1663.65 1729.83,1669.67 1729.83,1680.12 1738.28,1688.57 1741.43,1688.57 1749,1681 1749,1655.41 1751.6,1652.81 1771.04,1652.81 1777.66,1646.19 1795.17,1646.19 1806.44,1657.47 1806.44,1710.55 1810.86,1714.96 1813.26,1714.96 1826.66,1714.96 1828.98,1712.64 1828.98,1706.05 1831.3,1703.73 1838.26,1703.73 1840.58,1706.05 1840.58,1713.84 1842.9,1716.16 1849.86,1716.16 1852.18,1713.84 1852.18,1706.48 1854.5,1704.16 1861.46,1704.16 1863.78,1706.48 1863.78,1713.84 1866.1,1716.16 1873.06,1716.16 1875.38,1713.84 1875.38,1706.48 1877.7,1704.16 1884.66,1704.16 1886.98,1706.48 1886.98,1713.84 1889.3,1716.16 1896.26,1716.16 1898.58,1713.84 1898.58,1706.48 1900.9,1704.16 1907.86,1704.16 1910.18,1706.48 1910.18,1712.64 1912.5,1714.96 1916.67,1714.96 1917.47,1715.76 1932.23,1730.52 1933.1,1731.39 1945.63,1731.39 1947.95,1729.07 1947.95,1710.97 1950.27,1708.65 1957.23,1708.65 1959.55,1710.97 1959.55,1729.07 1961.87,1731.39 1968.83,1731.39 1971.15,1729.07 1971.15,1714.69 1973.47,1712.37 1980.43,1712.37 1982.75,1714.69 1982.75,1729.07 1985.07,1731.39 1992.03,1731.39 1994.35,1729.07 1994.35,1714.69 1996.67,1712.37 2003.63,1712.37 2005.95,1714.69 2005.95,1729.07 2008.27,1731.39 2032,1731.39 2065.32,1731.39 2071.41,1725.29 2071.41,1717.23 2071.41,1715.43 2073.73,1713.11 2082.49,1713.11 2084.81,1710.79 2084.81,1703.83 2082.49,1701.51 2047.63,1701.51 2045.31,1699.19 2045.31,1692.23 2047.63,1689.91 2080.24,1689.91 2082.56,1687.59 2082.56,1680.63 2080.24,1678.31 2047.63,1678.31 2045.31,1675.99 2045.31,1669.03 2047.63,1666.71 2077.59,1666.71 2079.91,1664.39 2079.91,1657.43 2077.59,1655.11 2073.73,1655.11 2071.41,1652.79 2071.41,1650.54 2071.41,1648.23 2073.64,1646 2083.39,1646 2085.19,1646 2087.51,1648.32 2087.51,1672.52 2089.83,1674.84 2096.79,1674.84 2099.11,1672.52 2099.11,1646.46 2101.43,1644.14 2108.39,1644.14 2110.71,1646.46 2110.71,1672.52 2113.03,1674.84 2119.99,1674.84 2122.31,1672.52 2122.31,1648.32 2124.63,1646 2135.15,1635.48 2146.52,1635.48 2154,1628 2159.92,1628 2183.97,1652.05 2183.97,1655.03 2180.99,1658.01 2179.57,1659.43 2172.57,1659.43 2168.41,1655.26 2158.16,1655.26 2137.4,1676.02 v1(2137.4,1679.73)
  Bottom Layer w5.8: v1(2137.4,1679.73) 2139.61,1677.52 R163.2@2139.61,1648.62
R_PR0_PRU1_GPIO12: R94.2 R139.1 R164.2 | length 2198.3
  Top Layer w5.8: v1(1383.75,1592.5) 1390.29,1592.5 1395.03,1592.5 1404.56,1582.97 R139.1@1404.56,1570.23 ; v1(2138.91,1617.19) 2138.91,1588.84 R94.2@2139.12,1588.62
  L08_SIG2 w3.6: v1(1383.75,1592.5) 1381.63,1590.38 1381.63,1572.86 1383.86,1570.63 1390.29,1570.63 1400.7,1570.63 1403.16,1570.63 1405.48,1572.95 1405.48,1588.31 1407.8,1590.63 1414.76,1590.63 1417.08,1588.31 1417.08,1572.95 1419.4,1570.63 1432.8,1570.63 1462.2,1570.63 1466.98,1575.42 1497.13,1605.56 1533.58,1642.01 1547.23,1642.01 1549.03,1642.01 1551.35,1644.33 1551.35,1662.56 1553.67,1664.88 1560.63,1664.88 1562.95,1662.56 1562.95,1641.93 1565.27,1639.61 1572.23,1639.61 1574.55,1641.93 1574.55,1662.56 1576.87,1664.88 1583.83,1664.88 1586.15,1662.56 1586.15,1641.93 1588.47,1639.61 1595.43,1639.61 1597.75,1641.93 1597.75,1662.56 1600.07,1664.88 1607.03,1664.88 1609.35,1662.56 1609.35,1641.93 1611.67,1639.61 1618.63,1639.61 1620.95,1641.93 1620.95,1662.56 1623.27,1664.88 1630.23,1664.88 1632.55,1662.56 1632.55,1641.93 1634.87,1639.61 1641.83,1639.61 1644.15,1641.93 1644.15,1662.56 1646.47,1664.88 1653.43,1664.88 1655.75,1662.56 1655.75,1641.93 1658.07,1639.61 1665.03,1639.61 1667.35,1641.93 1667.35,1662.56 1669.67,1664.88 1676.63,1664.88 1678.95,1662.56 1678.95,1641.93 1681.27,1639.61 1688.23,1639.61 1690.55,1641.93 1690.55,1662.56 1692.87,1664.88 1699.83,1664.88 1702.15,1662.56 1702.15,1644.33 1704.47,1642.01 1719.84,1642.01 1764.75,1642.01 1771.64,1635.12 1814.52,1635.12 1816.32,1635.12 1818.64,1637.44 1818.64,1663.09 1820.96,1665.41 1827.92,1665.41 1830.24,1663.09 1830.24,1635.31 1832.56,1632.99 1839.52,1632.99 1841.84,1635.31 1841.84,1666.9 1844.16,1669.22 1851.12,1669.22 1853.44,1666.9 1853.44,1615.98 1855.76,1613.66 1862.72,1613.66 1865.04,1615.98 1865.04,1682.64 1867.36,1684.96 1874.32,1684.96 1876.64,1682.64 1876.64,1592.73 1878.96,1590.41 1885.92,1590.41 1888.24,1592.73 1888.24,1682.64 1890.56,1684.96 1897.52,1684.96 1899.84,1682.64 1899.84,1614.16 1902.16,1611.84 1909.12,1611.84 1911.44,1614.16 1911.44,1632.8 1913.76,1635.12 1943,1635.12 1951.88,1635.12 1967.9,1619.1 1973.31,1619.1 1975.11,1619.1 1977.43,1621.42 1977.43,1636.78 1979.75,1639.1 1986.71,1639.1 1989.03,1636.78 1989.03,1589.92 1991.35,1587.6 1998.31,1587.6 2000.63,1589.92 2000.63,1625 2002.95,1627.32 2009.91,1627.32 2012.23,1625 2012.23,1589.92 2014.55,1587.6 2021.51,1587.6 2023.83,1589.92 2023.83,1617.02 2026.15,1619.34 2033.11,1619.34 2035.43,1617.02 2035.43,1588.64 2037.75,1586.32 2044.71,1586.32 2047.03,1588.64 2047.03,1636.78 2049.35,1639.1 2056.31,1639.1 2058.63,1636.78 2058.63,1588.64 2060.95,1586.32 2067.91,1586.32 2070.23,1588.64 2070.23,1634.08 2072.55,1636.4 2079.51,1636.4 2081.83,1634.08 2081.83,1588.64 2084.15,1586.32 2091.11,1586.32 2093.43,1588.64 2093.43,1632.22 2095.75,1634.54 2102.71,1634.54 2105.03,1632.22 2105.03,1621.42 2107.35,1619.1 2114,1619.1 2136.99,1619.1 v1(2138.91,1617.19)
  Bottom Layer w5.8: v1(2138.91,1617.19) 2139.26,1616.84 2139.26,1588.98 R164.2@2139.61,1588.62
R_PR0_PRU1_GPIO13: R95.2 R141.1 R167.2 | length 1646.6
  L08_SIG2 w3.6: v1(1468.74,1462.56) 1500.13,1493.96 1657.2,1493.96 1671.68,1479.48 1712.03,1479.48 1739.55,1507 1781.88,1507 1789.49,1514.62 1797.95,1514.62 1850.28,1462.29 1864.93,1462.29 1886.06,1441.16 2022.2,1441.16 2041.69,1421.67 2089.97,1421.67 2096.24,1427.94 2130.66,1427.94 2144.72,1442 2261.11,1442 2275.19,1427.91 2569,1427.91 2683.19,1313.72 2720.62,1276.3 2730.91,1276.3 v1(2732.35,1274.86)
  Bottom Layer w5.8: R141.1@1383.21,1516.39 1383.3,1516.3 1396.29,1516.3 1448.57,1464.02 1467.27,1464.02 v1(1468.74,1462.56) ; v1(2732.35,1274.86) 2732.35,1250.66 2738,1245 2747,1245 2754.95,1252.95 R167.2@2754.95,1284.92 2755.44,1284.43 R95.2@2795.77,1284.43
R_PR0_PRU1_GPIO14: R97.2 R142.1 R169.2 | length 2043.3
  Top Layer w5.8: R142.1@1412.85,1498.91 1413.64,1498.91 1419.01,1504.28 1419.01,1507.64 1423.03,1511.66 1430.54,1511.66 v1(1432.88,1514) ; R97.2@2139.12,1528.62 2139.12,1548.43 2144.74,1554.06 v1(2144.74,1555.88)
  L08_SIG2 w3.6: v1(1432.88,1514) 1432.88,1527.73 1441.37,1536.22 1450.84,1545.7 1454.12,1545.7 1462.95,1536.86 1466.24,1536.86 1471.16,1541.79 1471.16,1545.07 1462.32,1553.9 1462.32,1557.18 1467.25,1562.1 1470.53,1562.1 1479.36,1553.27 1482.64,1553.27 1487.56,1558.19 1487.56,1561.47 1478.73,1570.3 1478.73,1573.58 1489.15,1584.01 1535.16,1630.01 1550.02,1630.01 1563.42,1630.01 1565.74,1627.69 1565.74,1619.91 1568.06,1617.59 1575.02,1617.59 1577.34,1619.91 1577.34,1627.69 1579.66,1630.01 1586.62,1630.01 1588.94,1627.69 1588.94,1619.91 1591.26,1617.59 1598.22,1617.59 1600.54,1619.91 1600.54,1627.69 1602.86,1630.01 1609.82,1630.01 1612.14,1627.69 1612.14,1619.1 1614.46,1616.78 1621.42,1616.78 1623.74,1619.1 1623.74,1627.69 1626.06,1630.01 1633.02,1630.01 1635.34,1627.69 1635.34,1603.54 1637.66,1601.22 1644.62,1601.22 1646.94,1603.54 1646.94,1627.69 1649.26,1630.01 1656.22,1630.01 1658.54,1627.69 1658.54,1623.41 1660.86,1621.09 1667.82,1621.09 1670.14,1623.41 1670.14,1627.69 1672.46,1630.01 1677.45,1630.01 1763.17,1630.01 1769.79,1623.39 1827.38,1623.39 1930.89,1519.88 1936.65,1519.88 1938.87,1522.11 1938.87,1608.98 1941.19,1611.3 1948.15,1611.3 1950.47,1608.98 1950.47,1511.91 1952.79,1509.59 1959.75,1509.59 1962.07,1511.91 1962.07,1607.18 1964.39,1609.5 1971.35,1609.5 1973.67,1607.18 1973.67,1511.91 1975.99,1509.59 1982.95,1509.59 1985.27,1511.91 1985.27,1575.68 1987.59,1578 1994.55,1578 1996.87,1575.68 1996.87,1511.91 1999.19,1509.59 2006.15,1509.59 2008.47,1511.91 2008.47,1575.68 2010.79,1578 2017.75,1578 2020.07,1575.68 2020.07,1522.79 2022.39,1520.47 2029.35,1520.47 2031.67,1522.79 2031.67,1555.68 2033.99,1558 2045,1558 2046.8,1558 2049.12,1560.32 2049.12,1574.41 2051.44,1576.73 2058.4,1576.73 2060.72,1574.41 2060.72,1548.09 2063.04,1545.77 2070,1545.77 2072.32,1548.09 2072.32,1574.41 2074.64,1576.73 2081.6,1576.73 2083.92,1574.41 2083.92,1548.09 2086.24,1545.77 2093.2,1545.77 2095.52,1548.09 2095.52,1575.48 2097.84,1577.8 2104.8,1577.8 2107.12,1575.48 2107.12,1548.09 2109.44,1545.77 2116.4,1545.77 2118.72,1548.09 2118.72,1555.68 2118.72,1595.72 2121,1598 2127.77,1598 2130,1595.77 2130,1574.22 2132.23,1571.99 2135.37,1571.99 2140,1576.62 2140,1587.53 2142.11,1589.63 2148.76,1589.63 2150.87,1587.53 2150.87,1565.18 2144.74,1559.06 v1(2144.74,1555.88)
  Bottom Layer w5.8: v1(2144.74,1555.88) 2148.05,1555.88 2152.79,1551.13 2153.43,1551.13 2155.07,1549.5 R169.2@2155.07,1528.68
